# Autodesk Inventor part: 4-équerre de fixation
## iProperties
Created: 2011-02
Part Number: 4-équerre de fixation
Document SubType Name: Modeling
Designer: eric
Density: 1 g/cm^3
Author: eric
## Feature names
1. Base1
